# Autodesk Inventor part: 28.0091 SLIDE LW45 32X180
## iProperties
Created: 2007-04
Part Number: 28.0091 SLIDE LW45 32X180
Material: Aluminum-6061
Document SubType Name: Modeling
Designer: Andy Moles
Density: 2.71 g/cm^3
Author: Andy Moles
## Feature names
1. Extrusion1
